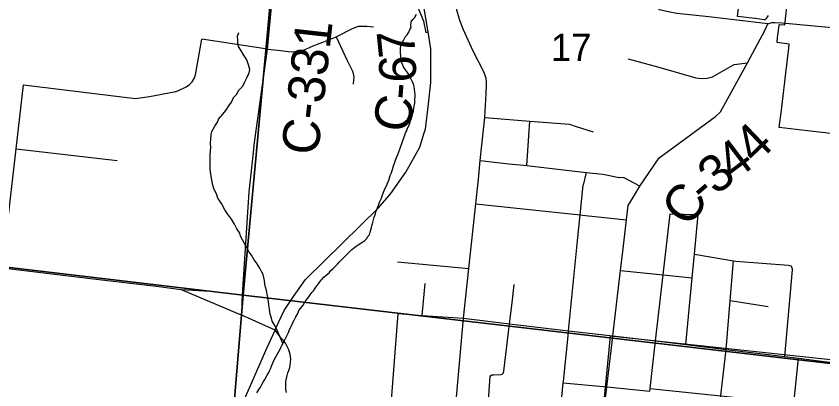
# Model space of a CAD drawing. Extents: x 0 to 34, y 0 to 22.
# Drawn here: x 3.161 to 3.782, y 18.905 to 19.192 of the extents above; entities that cross this region are included whole.
import ezdxf

# ---------------------------------------------------------------- set-up
doc = ezdxf.new("R2010")
doc.units = 0
for name, color, linetype in [('GM_X_City_Street', 7, 'Continuous'), ('GM_X_Corporation', 7, 'Continuous'), ('GM_X_County_Road', 7, 'Continuous'), ('GM_X_County_Road_Text', 7, 'Continuous'), ('GM_X_Interchange_Ramps', 7, 'Continuous'), ('GM_X_Minor_River', 7, 'Continuous'), ('GM_X_Rail_Line', 7, 'Continuous'), ('GM_X_Section', 7, 'Continuous'), ('GM_X_Section_Text', 7, 'Continuous'), ('GM_X_Township_Road', 7, 'Continuous')]:
    doc.layers.add(name, color=color, linetype=linetype)

msp = doc.modelspace()

# ---------------------------------------------------------------- linework, layer by layer
at = {"layer": 'GM_X_City_Street'}
for p, q in [((3.35444, 19.16674), (3.30413, 19.17432)), ((3.16126, 19.09019), (3.23878, 19.08107)), ((3.66429, 19.04019), (3.68572, 19.03962)), ((3.45456, 19.00321), (3.50942, 18.99817)), ((3.47344, 18.96219), (3.47579, 18.98668)), ((3.28804, 18.98214), (3.31056, 18.98076)), ((3.71037, 18.97363), (3.73957, 18.96903)), ((3.4472, 18.86107), (3.45508, 18.96348))]:
    msp.add_line(p, q, dxfattribs=at)
for points in [[(3.16694, 19.13938), (3.25287, 19.12876), (3.26373, 19.13018), (3.28405, 19.1341), (3.28556, 19.13457), (3.29201, 19.1376), (3.29458, 19.13949), (3.29667, 19.14166), (3.2982, 19.14417), (3.29908, 19.14691), (3.30413, 19.17432)], [(3.15071, 18.99879), (3.16126, 19.09019), (3.16694, 19.13938)], [(3.6408, 19.0613), (3.62881, 19.0677), (3.62826, 19.0679), (3.62506, 19.06808)], [(3.56869, 18.77065), (3.57247, 18.8108), (3.57275, 18.81379), (3.57543, 18.84685), (3.5772, 18.861), (3.57904, 18.88058), (3.58206, 18.91037), (3.58215, 18.91126), (3.58571, 18.94648), (3.58611, 18.95041), (3.59335, 19.02194), (3.59511, 19.03934), (3.59743, 19.06219)], [(3.51469, 19.04781), (3.59511, 19.03934), (3.599, 19.03894), (3.63061, 19.03561)], [(3.64882, 18.90594), (3.65303, 18.94251), (3.65888, 18.99327), (3.66429, 19.04019)], [(3.6764, 18.93969), (3.68118, 18.9909), (3.68288, 19.00917), (3.68572, 19.03962)], [(3.02154, 19.01463), (3.03644, 19.01261), (3.11491, 19.00312), (3.15071, 18.99879), (3.18669, 18.99443), (3.22267, 18.99008), (3.26892, 18.98448), (3.28804, 18.98214), (3.3348, 18.9624)], [(3.68288, 19.00917), (3.71287, 19.00397), (3.71472, 19.00381), (3.75536, 19.00072), (3.75724, 19.0001)], [(3.69927, 18.86737), (3.70312, 18.9004), (3.70338, 18.90268), (3.70726, 18.93597), (3.71037, 18.97363), (3.71287, 19.00397)], [(3.62605, 18.99676), (3.65888, 18.99327), (3.68118, 18.9909)], [(3.75243, 18.93052), (3.75831, 18.99703), (3.75826, 18.99771), (3.7581, 18.99839), (3.75771, 18.9993), (3.75724, 19.0001)], [(3.52142, 18.8531), (3.52577, 18.91528), (3.5263, 18.91603), (3.52707, 18.91638), (3.5286, 18.91652), (3.53392, 18.91676), (3.53493, 18.917), (3.53561, 18.91752), (3.536, 18.91807), (3.53627, 18.91936), (3.54071, 18.95577), (3.54266, 18.97178), (3.54437, 18.98582)], [(3.45508, 18.96348), (3.47344, 18.96219), (3.50536, 18.95994), (3.54071, 18.95577), (3.58611, 18.95041), (3.62013, 18.94639), (3.65303, 18.94251), (3.6764, 18.93969), (3.70726, 18.93597), (3.75243, 18.93052), (3.76309, 18.92923), (3.78276, 18.92686), (3.81319, 18.92319), (3.81473, 18.923), (3.85298, 18.91839), (3.85345, 18.91833)], [(3.36915, 18.90286), (3.36871, 18.90512), (3.3685, 18.90827), (3.36868, 18.91137), (3.36907, 18.9136), (3.36952, 18.9159), (3.37021, 18.91806), (3.37132, 18.92106), (3.37194, 18.92362), (3.37219, 18.92632), (3.37234, 18.92881), (3.37195, 18.93211), (3.37097, 18.93577), (3.36976, 18.9382), (3.36834, 18.94069), (3.36681, 18.94297), (3.36524, 18.94449), (3.36038, 18.9509)], [(3.75175, 18.82704), (3.7559, 18.86073), (3.75932, 18.89334), (3.75945, 18.89447), (3.76309, 18.92923)], [(3.58206, 18.91037), (3.61553, 18.90716), (3.64859, 18.90398), (3.64882, 18.90594), (3.68079, 18.90274), (3.70312, 18.9004), (3.75945, 18.89447), (3.81062, 18.88909), (3.82738, 18.88733), (3.85424, 18.8845), (3.88618, 18.88114)]]:
    msp.add_lwpolyline(points, dxfattribs=at)
at = {"layer": 'GM_X_Corporation'}
for points in [[(3.79005, 19.10162), (3.76977, 19.10403), (3.74822, 19.10659), (3.74979, 19.11986), (3.75109, 19.13084), (3.75235, 19.14153), (3.75348, 19.15085), (3.75367, 19.15234), (3.755, 19.16336), (3.7552, 19.16495), (3.75588, 19.17059), (3.74643, 19.17171), (3.74689, 19.17549), (3.74801, 19.18475), (3.74813, 19.18571), (3.75251, 19.18541), (3.75272, 19.18724), (3.75303, 19.19004), (3.75499, 19.20782)], [(3.73952, 19.19262), (3.73773, 19.18991), (3.73751, 19.18958), (3.73744, 19.18948), (3.73737, 19.18939), (3.73727, 19.18932), (3.73717, 19.18926), (3.73706, 19.18922), (3.73695, 19.18919), (3.73683, 19.18919), (3.73671, 19.18921), (3.7366, 19.18924), (3.73649, 19.18929), (3.72977, 19.1901), (3.7297, 19.19011), (3.71617, 19.19162), (3.71754, 19.20443)]]:
    msp.add_lwpolyline(points, dxfattribs=at)
at = {"layer": 'GM_X_County_Road'}
for points in [[(3.5167, 19.06668), (3.517, 19.06952), (3.51822, 19.08103), (3.52173, 19.11407), (3.52266, 19.13267), (3.52297, 19.13893), (3.52292, 19.14144), (3.52269, 19.14407), (3.52194, 19.14652), (3.52107, 19.14885), (3.51284, 19.16516), (3.50537, 19.18146), (3.50256, 19.18872), (3.49979, 19.19753), (3.49764, 19.21391), (3.49535, 19.23277), (3.49539, 19.24531), (3.49619, 19.25725), (3.5056, 19.31234), (3.51449, 19.37047), (3.51601, 19.37526), (3.51631, 19.37621)], [(3.47555, 19.10387), (3.47601, 19.10531), (3.47847, 19.12464), (3.48011, 19.14114), (3.48023, 19.16697), (3.47804, 19.18001), (3.47094, 19.22226), (3.46761, 19.25157), (3.46764, 19.25207)], [(3.34325, 19.08245), (3.34461, 19.09494), (3.35444, 19.16674), (3.35868, 19.21001), (3.35926, 19.21709), (3.3597, 19.22667)], [(3.73938, 19.18611), (3.74241, 19.1872), (3.74435, 19.1872)], [(3.74435, 19.1872), (3.74484, 19.1872), (3.75029, 19.18696), (3.79146, 19.18305)], [(3.63594, 19.05317), (3.6408, 19.0613), (3.65573, 19.08323), (3.69905, 19.11502), (3.70296, 19.11847), (3.7238, 19.15609), (3.73727, 19.18151), (3.73938, 19.18611)], [(3.38398, 18.98995), (3.38434, 18.9903), (3.43992, 19.04488), (3.44944, 19.05589), (3.46095, 19.07219), (3.47157, 19.09135), (3.47509, 19.10242), (3.47555, 19.10387)], [(3.33514, 18.97244), (3.33546, 18.98198), (3.3405, 19.05697), (3.34325, 19.08245)], [(3.49611, 18.8559), (3.50536, 18.95994), (3.50942, 18.99817), (3.51469, 19.04781), (3.5167, 19.06668)], [(3.62776, 19.01133), (3.63061, 19.03561), (3.63206, 19.04666), (3.63594, 19.05317)], [(3.61956, 18.94148), (3.62013, 18.94639), (3.62605, 18.99676), (3.62776, 19.01133)], [(3.36038, 18.9509), (3.36078, 18.95178), (3.36722, 18.966), (3.37464, 18.97667), (3.38362, 18.9896), (3.38398, 18.98995)], [(3.36038, 18.9509), (3.34781, 18.95633), (3.3348, 18.9624), (3.33514, 18.97244)], [(3.32677, 18.87513), (3.35434, 18.93757), (3.36038, 18.9509)], [(3.5724, 18.54012), (3.57673, 18.57752), (3.58785, 18.67354), (3.59132, 18.70349), (3.59466, 18.73233), (3.5965, 18.74756), (3.59893, 18.76779), (3.60039, 18.77985), (3.60407, 18.81047), (3.60803, 18.8433), (3.612, 18.87716), (3.61553, 18.90716), (3.61956, 18.94148)]]:
    msp.add_lwpolyline(points, dxfattribs=at)
at = {"layer": 'GM_X_Interchange_Ramps'}
msp.add_lwpolyline([(3.47065, 19.19769), (3.47449, 19.1881), (3.47642, 19.17951), (3.47804, 19.18001)], dxfattribs=at)
at = {"layer": 'GM_X_Minor_River'}
for points in [[(3.44845, 19.06791), (3.44889, 19.0696), (3.44952, 19.07109), (3.45016, 19.07278), (3.4506, 19.07428), (3.45124, 19.07596), (3.45169, 19.07784), (3.45212, 19.07916), (3.45319, 19.08215), (3.45402, 19.08402), (3.45466, 19.0857), (3.45634, 19.08982), (3.457, 19.09207), (3.45785, 19.09431), (3.4585, 19.09638), (3.45977, 19.09975), (3.46042, 19.10162), (3.46104, 19.10293), (3.46166, 19.10423), (3.4623, 19.10591), (3.46313, 19.10778), (3.46375, 19.10908), (3.4642, 19.11078), (3.46504, 19.11283), (3.46549, 19.11471), (3.46636, 19.11753), (3.4668, 19.11903), (3.46709, 19.12149), (3.4678, 19.12507), (3.46791, 19.12792), (3.46819, 19.13019), (3.46807, 19.1319), (3.46794, 19.13343), (3.46747, 19.13611), (3.46735, 19.13782), (3.46686, 19.13974), (3.46598, 19.14149), (3.46458, 19.14459), (3.46316, 19.14712), (3.46227, 19.14868), (3.46064, 19.15084), (3.45922, 19.15318), (3.45781, 19.15609), (3.45732, 19.1582), (3.45706, 19.16106), (3.4568, 19.1643), (3.45674, 19.16753), (3.45741, 19.16998), (3.45825, 19.17203), (3.45926, 19.1737), (3.4607, 19.1763), (3.46189, 19.17777), (3.46311, 19.17981), (3.46395, 19.18187), (3.46515, 19.18334), (3.46465, 19.18507), (3.46513, 19.18771), (3.46635, 19.18956), (3.46754, 19.19084), (3.46916, 19.19343)], [(3.36637, 18.94056), (3.36158, 18.9512), (3.36054, 18.9539), (3.35822, 18.95761), (3.35756, 18.96011), (3.35653, 18.963), (3.35611, 18.96682), (3.35547, 18.96989), (3.3552, 18.97275), (3.35462, 18.97715), (3.35383, 18.98117), (3.35298, 18.98387), (3.3525, 18.98617), (3.35224, 18.98903), (3.35109, 18.99364), (3.34985, 18.99597), (3.34861, 18.99831), (3.34611, 19.0024), (3.34431, 19.00495), (3.34217, 19.00846), (3.34036, 19.01081), (3.33789, 19.01548), (3.33522, 19.02015), (3.33363, 19.02307), (3.33315, 19.02537), (3.33081, 19.0287), (3.32904, 19.03219), (3.32692, 19.03608), (3.32366, 19.04021), (3.32169, 19.04314), (3.31903, 19.04819), (3.31635, 19.0523), (3.31533, 19.05557), (3.31356, 19.05887), (3.31255, 19.06215), (3.31175, 19.06598), (3.31112, 19.06924), (3.31066, 19.07211), (3.31041, 19.07535), (3.31034, 19.07839), (3.31032, 19.08258), (3.31044, 19.08561), (3.31085, 19.0913), (3.31077, 19.09396), (3.31092, 19.09795), (3.31121, 19.1004), (3.3115, 19.10286), (3.31396, 19.10751), (3.31598, 19.11066), (3.31683, 19.1129), (3.32021, 19.11676), (3.32241, 19.11952), (3.32483, 19.12303), (3.32685, 19.12598), (3.32832, 19.12953), (3.33068, 19.13172), (3.33253, 19.13525), (3.3355, 19.13817), (3.33715, 19.14152), (3.33882, 19.14525), (3.34046, 19.14841), (3.34094, 19.15106), (3.33995, 19.15471), (3.33857, 19.15838), (3.33661, 19.1615), (3.33393, 19.16598), (3.33233, 19.16871), (3.33167, 19.17121), (3.33157, 19.17349), (3.3315, 19.17673), (3.33256, 19.17934)], [(3.34636, 18.9026), (3.34799, 18.90539), (3.34901, 18.90706), (3.35004, 18.9091), (3.35146, 18.91132), (3.35247, 18.91299), (3.35431, 18.91634), (3.35553, 18.91838), (3.35615, 18.91968), (3.35678, 18.92118), (3.35762, 18.92304), (3.35971, 18.9279), (3.36094, 18.93032), (3.36422, 18.93626), (3.36484, 18.93757), (3.36566, 18.93906), (3.36752, 18.94297), (3.36855, 18.94483), (3.36958, 18.94707), (3.37061, 18.94911), (3.37124, 18.95061), (3.37228, 18.95285), (3.37312, 18.95471), (3.37374, 18.95621), (3.37497, 18.95844), (3.37622, 18.96105), (3.37784, 18.96364), (3.37869, 18.96589), (3.38088, 18.96865), (3.38189, 18.97012), (3.38291, 18.97179), (3.38412, 18.97364), (3.38552, 18.9753), (3.38673, 18.97715), (3.38873, 18.97972), (3.38992, 18.981), (3.39114, 18.98304), (3.39254, 18.98489), (3.39374, 18.98636), (3.39456, 18.98765), (3.39615, 18.98949), (3.39794, 18.99151), (3.39971, 18.99314), (3.40206, 18.99495), (3.40307, 18.99642), (3.40504, 18.99805), (3.40662, 18.9997), (3.4084, 19.00152), (3.4096, 19.003), (3.41118, 19.00445), (3.41296, 19.00628), (3.41434, 19.00755), (3.41553, 19.00883), (3.41711, 19.01048), (3.41949, 19.01285), (3.42263, 19.01538), (3.42438, 19.01645), (3.4271, 19.01804), (3.42926, 19.01966), (3.43064, 19.02094), (3.43166, 19.0228), (3.43285, 19.02408), (3.4335, 19.02614), (3.43395, 19.02783), (3.4344, 19.02972), (3.43484, 19.03122), (3.43527, 19.03253), (3.43615, 19.03554), (3.43661, 19.03761), (3.43748, 19.04023), (3.43773, 19.04174), (3.43896, 19.04416), (3.43977, 19.04546), (3.44002, 19.04678), (3.44068, 19.04922), (3.44213, 19.0522), (3.44277, 19.05408), (3.44364, 19.0567), (3.44447, 19.05857), (3.44655, 19.06304), (3.4478, 19.06603), (3.44845, 19.06791)]]:
    msp.add_lwpolyline(points, dxfattribs=at)
at = {"layer": 'GM_X_Rail_Line'}
msp.add_lwpolyline([(3.88799, 18.91714), (3.6182, 18.94624), (3.60814, 18.84411)], dxfattribs=at)
at = {"layer": 'GM_X_Section'}
for points in [[(2.88606, 19.54156), (3.38246, 19.48109), (3.33585, 18.97757), (2.84187, 19.03609)], [(3.38246, 19.48109), (3.89779, 19.42002), (3.84478, 18.91854), (3.33585, 18.97757)], [(2.84187, 19.03609), (3.33585, 18.97757), (3.29405, 18.47716), (2.79274, 18.52978)], [(3.33585, 18.97757), (3.84478, 18.91854), (3.78896, 18.4239), (3.29405, 18.47716)]]:
    msp.add_lwpolyline(points, close=True, dxfattribs=at)
at = {"layer": 'GM_X_Township_Road'}
for p, q in [((3.55393, 19.07738), (3.55628, 19.11145)), ((3.59958, 19.07196), (3.59743, 19.06219))]:
    msp.add_line(p, q, dxfattribs=at)
for points in [[(3.73938, 19.18611), (3.69403, 19.19144), (3.6693, 19.19411), (3.66409, 19.1952), (3.65828, 19.19633), (3.65584, 19.1969), (3.65463, 19.19917)], [(3.35444, 19.16674), (3.36251, 19.16579), (3.37058, 19.1649), (3.37403, 19.16461), (3.3817, 19.16569), (3.38958, 19.16914), (3.40041, 19.17327), (3.40746, 19.17601), (3.4199, 19.18262), (3.42463, 19.1844), (3.43089, 19.18422), (3.43595, 19.1839)], [(3.40746, 19.17601), (3.4157, 19.15783), (3.41871, 19.15233), (3.41998, 19.14977), (3.42052, 19.14795), (3.42086, 19.14511), (3.42077, 19.14321), (3.42048, 19.13988)], [(3.63193, 19.15913), (3.65555, 19.15295), (3.68405, 19.14458), (3.6881, 19.14423), (3.69275, 19.14446), (3.69678, 19.14546), (3.71301, 19.15455)], [(3.71301, 19.15455), (3.71347, 19.15481), (3.7238, 19.15609)], [(3.52173, 19.11407), (3.55628, 19.11145), (3.58675, 19.10914), (3.59108, 19.10753), (3.60504, 19.10307)], [(3.51822, 19.08103), (3.54011, 19.07866), (3.54881, 19.07786)], [(3.54881, 19.07786), (3.55393, 19.07738), (3.59958, 19.07196), (3.61237, 19.07053)], [(3.61237, 19.07053), (3.61365, 19.07039), (3.62506, 19.06808)]]:
    msp.add_lwpolyline(points, dxfattribs=at)

# ---------------------------------------------------------------- texts
at = {"layer": 'GM_X_County_Road_Text'}
for s, height, rotation, p in [('C-331', 0.028409, 83.66831, (3.39328, 19.08446)), ('7', 0.02841, 95.78186, (3.46872, 19.16173)), ('6', 0.02841, 88.98809, (3.46857, 19.1407)), ('-', 0.02841, 85.38852, (3.46755, 19.12723)), ('C', 0.02841, 79.93143, (3.46312, 19.1015)), ('4', 0.02841, 43.76408, (3.73001, 19.07747)), ('4', 0.02841, 37.16912, (3.71335, 19.06459)), ('3', 0.02841, 37.3211, (3.69945, 19.05399)), ('C', 0.02841, 55.22572, (3.67895, 19.02886)), ('-', 0.02841, 40.96196, (3.69101, 19.04664))]:
    msp.add_text(s, height=height, rotation=rotation, dxfattribs=at).set_placement(p)
at = {"layer": 'GM_X_Section_Text'}
msp.add_text('17', height=0.020928, rotation=0.00001, dxfattribs=at).set_placement((3.57254, 19.15757))

doc.saveas('drawing.dxf')
